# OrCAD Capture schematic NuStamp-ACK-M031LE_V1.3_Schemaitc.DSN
size Custom; title: NuStamp-ACK_M031LE3AE; rev: v1.1; note: NuStamp-ACK_M031LE3AE
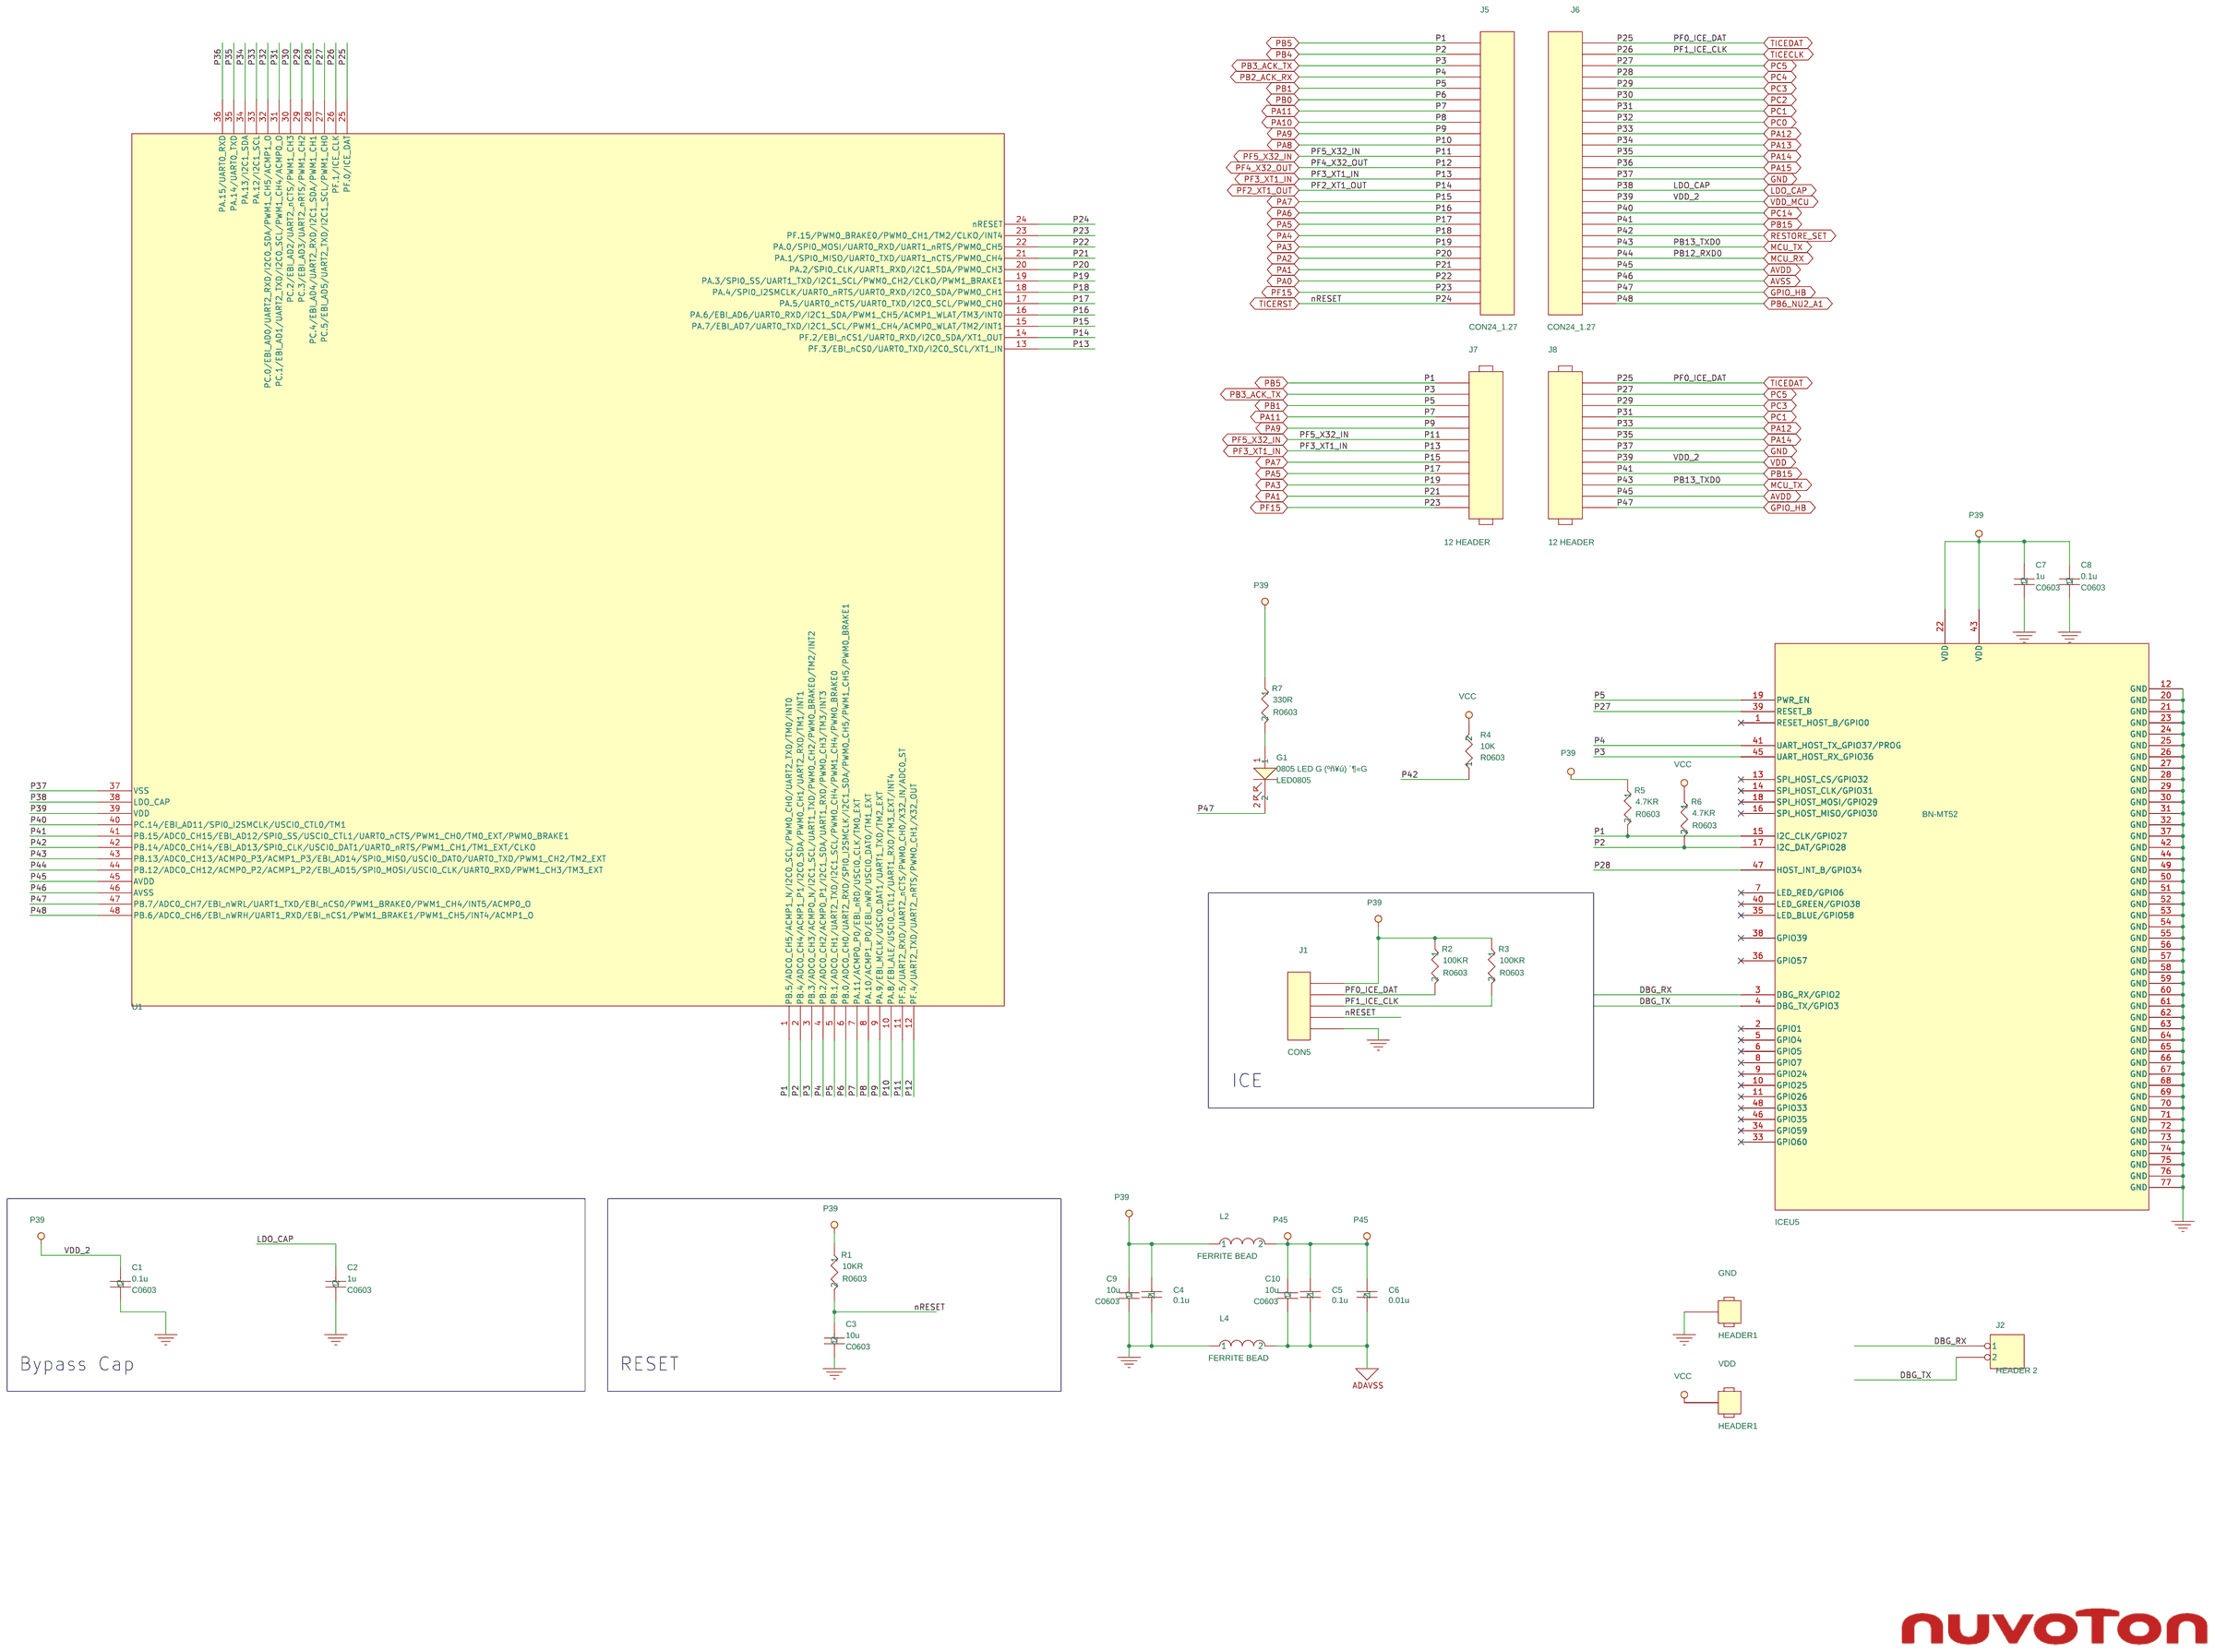
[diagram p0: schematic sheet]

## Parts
C1  0.1u  [C0603]
C2  1u  [C0603]
C3  10u  [C0603]
C4  0.1u  [C0603]
C5  0.1u  [C0603]
C6  0.01u  [C0603]
C7  1u  [C0603]
C8  0.1u  [C0603]
C9  10u  [C0603]
C10  10u  [C0603]
G1  0805 LED G (ºñ¥ú) ´¶«G  [LED0805]
GND  HEADER1
ICEU5  M48SSIDAE  [MODULE_ACK_16x23_PIN78_ANTENNA]
J1  CON5  [HEADER05]
J2  HEADER 2  [HEADER2X1]
J5  CON24_1.27
J6  CON24_1.27
J7  12 HEADER  [CON12_2.54]
J8  12 HEADER  [CON12_2.54]
L2  FERRITE BEAD  [L0603]
L4  FERRITE BEAD  [L0603]
R1  10KR  [R0603]
R2  100KR  [R0603]
R3  100KR  [R0603]
R4  10K  [R0603]
R5  4.7KR  [R0603]
R6  4.7KR  [R0603]
R7  330R  [R0603]
U1  M031LE3AE  [MCU_LQFP_48]
VDD  HEADER1

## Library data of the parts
C1 = CAP-C_4: Package: 0603; element_no: C0004
C2 = CAP-C_2: Package: 0603; element_no: C0006
C3 = CAP-C_5: Package: 0603; element_no: C0006
C4 = C_0.1u: element_no: C0004
C5 = C_0.1u_1: element_no: C0004
C6 = C_0.1u_2: element_no: C0003
C7 = CAP-C_3: Package: 0603; element_no: C0006
C8 = CAP-C: Package: 0603; element_no: C0004
C9 = CAP-C_1: Package: 0603; element_no: C0006
C10 = CAP-C_6: Package: 0603; element_no: C0006
G1 = LED_0: Package: KP-2012; Vendor: Kingbright
GND VDD = HEADER_1
ICEU5 = M487SIDAE_7: M487SIDAE: BN-MT52
J1 = CON5
J2 = HEADER_2
J5 J6 = CON24
J7 J8 = 12_HEADER
L2 = FERRITE_BEAD_1
L4 = FERRITE_BEAD
R1 = R_0_2: Package: 0603
R2 = R_0_3: Package: 0603
R3 = R_0_4: Package: 0603
R4 = R_0_6: Package: 0603
R5 = R_0_5: Package: 0603
R6 = R_0: Package: 0603
R7 = R_0_1: Package: 0603
U1 = M031LE3AE

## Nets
AVDD: C5.1 C6.1 C10.2 J6.21 J8.11 L2.2 U1.45(AVDD)
AVSS: C5.2 C6.2 C10.1 J6.22 L4.2 U1.46(AVSS)
GND: C1.1 C2.1 C3.1 C4.2 C7.1 C8.1 C9.1 GND.1 ICEU5.12(GND) ICEU5.20(GND) ICEU5.21(GND) ICEU5.23(GND) ICEU5.24(GND) ICEU5.25(GND) ICEU5.26(GND) ICEU5.27(GND) ICEU5.28(GND) ICEU5.29(GND) ICEU5.30(GND) ICEU5.31(GND) ICEU5.32(GND) ICEU5.37(GND) ICEU5.42(GND) ICEU5.44(GND) ICEU5.49(GND) ICEU5.50(GND) ICEU5.51(GND) ICEU5.52(GND) ICEU5.53(GND) ICEU5.54(GND) ICEU5.55(GND) ICEU5.56(GND) ICEU5.57(GND) ICEU5.58(GND) ICEU5.59(GND) ICEU5.60(GND) ICEU5.61(GND) ICEU5.62(GND) ICEU5.63(GND) ICEU5.64(GND) ICEU5.65(GND) ICEU5.66(GND) ICEU5.67(GND) ICEU5.68(GND) ICEU5.69(GND) ICEU5.70(GND) ICEU5.71(GND) ICEU5.72(GND) ICEU5.73(GND) ICEU5.74(GND) ICEU5.75(GND) ICEU5.76(GND) ICEU5.77(GND) J1.5 J6.13 J8.7 L4.1 U1.37(VSS)
VDD: C1.2 C4.1 C7.2 C8.2 C9.2 ICEU5.22(VDD) ICEU5.43(VDD) J1.1 J6.15 J8.8 L2.1 R1.1 R2.1 R3.1 R4.2 R5.1 R6.1 R7.1 U1.39(VDD) VDD.1
DBG_RX: ICEU5.3(DBG_RX/GPIO2) J2.1
DBG_TX: ICEU5.4(DBG_TX/GPIO3) J2.2
GPIO_HB: G1.2 J6.23 J8.12 U1.47(PB.7/ADC0_CH7/EBI_nWRL/UART1_TXD/EBI_nCS0/PWM1_BRAKE0/PWM1_CH4/INT5/ACMP0_O)
LDO_CAP: C2.2 J6.14 U1.38(LDO_CAP)
MCU_RX: J6.20 U1.44(PB.12/ADC0_CH12/ACMP0_P2/ACMP1_P2/EBI_AD15/SPI0_MOSI/USCI0_CLK/UART0_RXD/PWM1_CH3/TM3_EXT)
MCU_TX: J6.19 J8.10 U1.43(PB.13/ADC0_CH13/ACMP0_P3/ACMP1_P3/EBI_AD14/SPI0_MISO/USCI0_DAT0/UART0_TXD/PWM1_CH2/TM2_EXT)
PA0: J5.22 U1.22(PA.0/SPI0_MOSI/UART0_RXD/UART1_nRTS/PWM0_CH5)
PA1: J5.21 J7.11 U1.21(PA.1/SPI0_MISO/UART0_TXD/UART1_nCTS/PWM0_CH4)
PA2: J5.20 U1.20(PA.2/SPI0_CLK/UART1_RXD/I2C1_SDA/PWM0_CH3)
PA3: J5.19 J7.10 U1.19(PA.3/SPI0_SS/UART1_TXD/I2C1_SCL/PWM0_CH2/CLKO/PWM1_BRAKE1)
PA4: J5.18 U1.18(PA.4/SPI0_I2SMCLK/UART0_nRTS/UART0_RXD/I2C0_SDA/PWM0_CH1)
PA5: J5.17 J7.9 U1.17(PA.5/UART0_nCTS/UART0_TXD/I2C0_SCL/PWM0_CH0)
PA6: J5.16 U1.16(PA.6/EBI_AD6/UART0_RXD/I2C1_SDA/PWM1_CH5/ACMP1_WLAT/TM3/INT0)
PA7: J5.15 J7.8 U1.15(PA.7/EBI_AD7/UART0_TXD/I2C1_SCL/PWM1_CH4/ACMP0_WLAT/TM2/INT1)
PA8: J5.10 U1.10(PA.8/EBI_ALE/USCI0_CTL1/UART1_RXD/TM3_EXT/INT4)
PA9: J5.9 J7.5 U1.9(PA.9/EBI_MCLK/USCI0_DAT1/UART1_TXD/TM2_EXT)
PA10: J5.8 U1.8(PA.10/ACMP1_P0/EBI_nWR/USCI0_DAT0/TM1_EXT)
PA11: J5.7 J7.4 U1.7(PA.11/ACMP0_P0/EBI_nRD/USCI0_CLK/TM0_EXT)
PA12: J6.9 J8.5 U1.33(PA.12/I2C1_SCL)
PA13: J6.10 U1.34(PA.13/I2C1_SDA)
PA14: J6.11 J8.6 U1.35(PA.14/UART0_TXD)
PA15: J6.12 U1.36(PA.15/UART0_RXD)
PB0: J5.6 U1.6(PB.0/ADC0_CH0/UART2_RXD/SPI0_I2SMCLK/I2C1_SDA/PWM0_CH5/PWM1_CH5/PWM0_BRAKE1)
PB1: ICEU5.19(PWR_EN) J5.5 J7.3 U1.5(PB.1/ADC0_CH1/UART2_TXD/I2C1_SCL/PWM0_CH4/PWM1_CH4/PWM0_BRAKE0)
PB2_ACK_RX: ICEU5.41(UART_HOST_TX_GPIO37/PROG) J5.4 U1.4(PB.2/ADC0_CH2/ACMP0_P1/I2C1_SDA/UART1_RXD/PWM0_CH3/TM3/INT3)
PB3_ACK_TX: ICEU5.45(UART_HOST_RX_GPIO36) J5.3 J7.2 U1.3(PB.3/ADC0_CH3/ACMP0_N/I2C1_SCL/UART1_TXD/PWM0_CH2/PWM0_BRAKE0/TM2/INT2)
PB4: ICEU5.17(I2C_DAT/GPIO28) J5.2 R6.2 U1.2(PB.4/ADC0_CH4/ACMP1_P1/I2C0_SDA/PWM0_CH1/UART2_RXD/TM1/INT1)
PB5: ICEU5.15(I2C_CLK/GPIO27) J5.1 J7.1 R5.2 U1.1(PB.5/ADC0_CH5/ACMP1_N/I2C0_SCL/PWM0_CH0/UART2_TXD/TM0/INT0)
PB6_NU2_A1: J6.24 U1.48(PB.6/ADC0_CH6/EBI_nWRH/UART1_RXD/EBI_nCS1/PWM1_BRAKE1/PWM1_CH5/INT4/ACMP1_O)
PB15: J6.17 J8.9 U1.41(PB.15/ADC0_CH15/EBI_AD12/SPI0_SS/USCI0_CTL1/UART0_nCTS/PWM1_CH0/TM0_EXT/PWM0_BRAKE1)
PC0: J6.8 U1.32(PC.0/EBI_AD0/UART2_RXD/I2C0_SDA/PWM1_CH5/ACMP1_O)
PC1: J6.7 J8.4 U1.31(PC.1/EBI_AD1/UART2_TXD/I2C0_SCL/PWM1_CH4/ACMP0_O)
PC2: J6.6 U1.30(PC.2/EBI_AD2/UART2_nCTS/PWM1_CH3)
PC3: J6.5 J8.3 U1.29(PC.3/EBI_AD3/UART2_nRTS/PWM1_CH2)
PC4: ICEU5.47(HOST_INT_B/GPIO34) J6.4 U1.28(PC.4/EBI_AD4/UART2_RXD/I2C1_SDA/PWM1_CH1)
PC5: ICEU5.39(RESET_B) J6.3 J8.2 U1.27(PC.5/EBI_AD5/UART2_TXD/I2C1_SCL/PWM1_CH0)
PC14: J6.16 U1.40(PC.14/EBI_AD11/SPI0_I2SMCLK/USCI0_CTL0/TM1)
PF2_XT1_OUT: J5.14 U1.14(PF.2/EBI_nCS1/UART0_RXD/I2C0_SDA/XT1_OUT)
PF3_XT1_IN: J5.13 J7.7 U1.13(PF.3/EBI_nCS0/UART0_TXD/I2C0_SCL/XT1_IN)
PF4_X32_OUT: J5.12 U1.12(PF.4/UART2_TXD/UART2_nRTS/PWM0_CH1/X32_OUT)
PF5_X32_IN: J5.11 J7.6 U1.11(PF.5/UART2_RXD/UART2_nCTS/PWM0_CH0/X32_IN/ADC0_ST)
PF15: J5.23 J7.12 U1.23(PF.15/PWM0_BRAKE0/PWM0_CH1/TM2/CLKO/INT4)
RESTORE_SET: J6.18 R4.1 U1.42(PB.14/ADC0_CH14/EBI_AD13/SPI0_CLK/USCI0_DAT1/UART0_nRTS/PWM1_CH1/TM1_EXT/CLKO)
TICECLK: J1.3 J6.2 R3.2 U1.26(PF.1/ICE_CLK)
TICEDAT: J1.2 J6.1 J8.1 R2.2 U1.25(PF.0/ICE_DAT)
TICERST: C3.2 J1.4 J5.24 R1.2 U1.24(nRESET)
N17270153: G1.1 R7.2

Not connected (* = marked no-connect by the designer): ICEU5 1(RESET_HOST_B/GPIO0)* 2(GPIO1)* 5(GPIO4)* 6(GPIO5)* 7(LED_RED/GPIO6)* 8(GPIO7)* 9(GPIO24)* 10(GPIO25)* 11(GPIO26)* 13(SPI_HOST_CS/GPIO32)* 14(SPI_HOST_CLK/GPIO31)* 16(SPI_HOST_MISO/GPIO30)* 18(SPI_HOST_MOSI/GPIO29)* 33(GPIO60)* 34(GPIO59)* 35(LED_BLUE/GPIO58)* 36(GPIO57)* 38(GPIO39)* 40(LED_GREEN/GPIO38)* 46(GPIO35)* 48(GPIO33)*

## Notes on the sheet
- ICE
- Bypass Cap
- RESET
